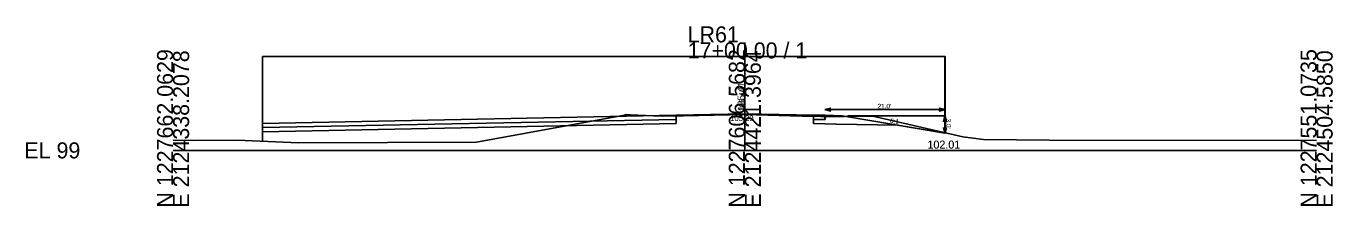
# Model space of a CAD drawing. Extents: x 2126751 to 2128979, y 1225108 to 1234639.
# Drawn here: x 2127750.9 to 2127979.4, y 1232107.5 to 1232138.9 of the extents above; entities that cross this region are included whole.
import ezdxf

# ---------------------------------------------------------------- set-up
doc = ezdxf.new("R2010")
doc.units = 0
for name, color, linetype in [('XS_CELL', 7, 'Continuous'), ('XS_M_DITCH', 7, 'Continuous'), ('XS_P_FINISHED_GRADE', 7, 'Continuous'), ('XS_P_FINISHED_GRADE_ELEV_TX', 7, 'Continuous'), ('XS_P_SUBGRADE_GRANULAR', 7, 'Continuous'), ('XS_P_SUBGRADE_LEVELING', 7, 'Continuous'), ('XS_P_SUBGRADE_PAVEMENT', 7, 'Continuous'), ('XS_P_TX_CLEARZONE', 7, 'Continuous'), ('XS_P_TX_DCH', 7, 'Continuous'), ('XS_P_TX_FS_BS', 7, 'Continuous'), ('XS_X_GROUND', 7, 'Continuous'), ('XS_X_GROUND_TX', 7, 'Continuous')]:
    doc.layers.add(name, color=color, linetype=linetype)

msp = doc.modelspace()

# ---------------------------------------------------------------- linework, layer by layer
at = {"layer": 'XS_CELL'}
for p, q in [((2127876.61, 1232117.21), (2127876.61, 1232136.08)), ((2127776.61, 1232117.21), (2127876.61, 1232117.21)), ((2127876.61, 1232117.21), (2127976.61, 1232117.21))]:
    msp.add_line(p, q, dxfattribs=at)
at = {"layer": 'XS_M_DITCH'}
for p, q in [((2127792.23, 1232118.82), (2127792.23, 1232133.62)), ((2127792.23, 1232133.62), (2127911.61, 1232133.62)), ((2127792.23, 1232118.82), (2127792.23, 1232133.62)), ((2127792.23, 1232133.62), (2127911.63, 1232133.62)), ((2127911.61, 1232133.62), (2127911.61, 1232120.22)), ((2127911.63, 1232133.62), (2127911.63, 1232120.22))]:
    msp.add_line(p, q, dxfattribs=at)
at = {"layer": 'XS_P_FINISHED_GRADE'}
for p, q in [((2127864.61, 1232123.38), (2127792.23, 1232121.93)), ((2127864.61, 1232123.38), (2127792.23, 1232121.93)), ((2127864.61, 1232123.38), (2127876.61, 1232123.62)), ((2127864.61, 1232123.38), (2127876.61, 1232123.62)), ((2127876.61, 1232123.62), (2127888.61, 1232123.38)), ((2127876.61, 1232123.62), (2127888.61, 1232123.38)), ((2127888.61, 1232123.38), (2127890.61, 1232123.34)), ((2127888.61, 1232123.38), (2127890.63, 1232123.34)), ((2127890.61, 1232123.34), (2127893.61, 1232123.22)), ((2127890.63, 1232123.34), (2127893.63, 1232123.22)), ((2127893.61, 1232123.22), (2127911.61, 1232120.22)), ((2127893.63, 1232123.22), (2127911.63, 1232120.22)), ((2127792.23, 1232121.93), (2127792.23, 1232118.82)), ((2127792.23, 1232121.93), (2127792.23, 1232118.82)), ((2127911.61, 1232120.22), (2127911.7, 1232120.25)), ((2127911.63, 1232120.22), (2127911.71, 1232120.25))]:
    msp.add_line(p, q, dxfattribs=at)
at = {"layer": 'XS_P_SUBGRADE_GRANULAR'}
for p, q in [((2127864.61, 1232121.88), (2127864.61, 1232122.63)), ((2127864.61, 1232121.88), (2127864.61, 1232122.63)), ((2127888.61, 1232121.88), (2127888.61, 1232122.63)), ((2127888.61, 1232121.88), (2127888.61, 1232122.63)), ((2127864.61, 1232121.88), (2127792.23, 1232120.43)), ((2127864.61, 1232121.88), (2127792.23, 1232120.43)), ((2127888.61, 1232121.88), (2127890.61, 1232121.84)), ((2127888.61, 1232121.88), (2127890.63, 1232121.84)), ((2127890.61, 1232121.84), (2127892.61, 1232121.8)), ((2127890.63, 1232121.84), (2127892.63, 1232121.8)), ((2127892.61, 1232121.8), (2127903.43, 1232121.59)), ((2127892.63, 1232121.8), (2127903.45, 1232121.59))]:
    msp.add_line(p, q, dxfattribs=at)
at = {"layer": 'XS_P_SUBGRADE_LEVELING'}
for p, q in [((2127864.61, 1232123.38), (2127864.61, 1232123.23)), ((2127864.61, 1232123.38), (2127864.61, 1232123.23)), ((2127864.61, 1232123.23), (2127865.9, 1232123.26)), ((2127864.61, 1232123.23), (2127865.9, 1232123.26)), ((2127865.9, 1232123.26), (2127876.58, 1232123.5)), ((2127865.9, 1232123.26), (2127876.58, 1232123.5)), ((2127876.58, 1232123.5), (2127888.61, 1232123.14)), ((2127876.58, 1232123.5), (2127888.61, 1232123.14)), ((2127888.61, 1232123.38), (2127888.61, 1232123.14)), ((2127888.61, 1232123.38), (2127888.61, 1232123.14))]:
    msp.add_line(p, q, dxfattribs=at)
at = {"layer": 'XS_P_SUBGRADE_PAVEMENT'}
for p, q in [((2127864.61, 1232122.63), (2127792.23, 1232121.18)), ((2127864.61, 1232122.63), (2127792.23, 1232121.18)), ((2127864.61, 1232122.63), (2127864.61, 1232123.23)), ((2127888.61, 1232122.63), (2127888.61, 1232123.14)), ((2127888.61, 1232122.63), (2127888.61, 1232123.14)), ((2127888.61, 1232122.63), (2127890.61, 1232122.59)), ((2127888.61, 1232122.63), (2127890.63, 1232122.59)), ((2127890.61, 1232122.59), (2127890.61, 1232123.34)), ((2127890.63, 1232122.59), (2127890.63, 1232123.34))]:
    msp.add_line(p, q, dxfattribs=at)
at = {"layer": 'XS_P_TX_CLEARZONE'}
for p, q in [((2127890.61, 1232124.34), (2127891.61, 1232124.59)), ((2127890.63, 1232124.34), (2127891.63, 1232124.59)), ((2127911.61, 1232124.34), (2127910.61, 1232124.59)), ((2127911.63, 1232124.34), (2127910.63, 1232124.59)), ((2127890.61, 1232124.34), (2127891.61, 1232124.09)), ((2127890.61, 1232124.34), (2127911.61, 1232124.34)), ((2127890.63, 1232124.34), (2127891.63, 1232124.09)), ((2127890.63, 1232124.34), (2127911.63, 1232124.34)), ((2127894.61, 1232123.22), (2127911.61, 1232123.22)), ((2127894.63, 1232123.22), (2127911.63, 1232123.22)), ((2127911.61, 1232124.34), (2127910.61, 1232124.09)), ((2127911.63, 1232124.34), (2127910.63, 1232124.09)), ((2127911.61, 1232123.22), (2127911.36, 1232122.22)), ((2127911.63, 1232123.22), (2127911.38, 1232122.22)), ((2127911.61, 1232123.22), (2127911.61, 1232120.22)), ((2127911.61, 1232123.22), (2127911.86, 1232122.22)), ((2127911.63, 1232123.22), (2127911.63, 1232120.22)), ((2127911.63, 1232123.22), (2127911.88, 1232122.22)), ((2127911.61, 1232120.22), (2127911.36, 1232121.22)), ((2127911.63, 1232120.22), (2127911.38, 1232121.22)), ((2127911.61, 1232120.22), (2127911.86, 1232121.22)), ((2127911.63, 1232120.22), (2127911.88, 1232121.22))]:
    msp.add_line(p, q, dxfattribs=at)
at = {"layer": 'XS_X_GROUND'}
for p, q in [((2127829.66, 1232118.65), (2127855.57, 1232123.38)), ((2127855.57, 1232123.38), (2127855.94, 1232123.47)), ((2127855.94, 1232123.47), (2127856.56, 1232123.44)), ((2127856.56, 1232123.44), (2127861.96, 1232123.17)), ((2127861.96, 1232123.17), (2127865.9, 1232123.26)), ((2127865.9, 1232123.26), (2127876.58, 1232123.5)), ((2127876.58, 1232123.5), (2127889.88, 1232123.11)), ((2127889.88, 1232123.11), (2127890.83, 1232123.07)), ((2127890.83, 1232123.07), (2127894.02, 1232123.12)), ((2127894.02, 1232123.12), (2127898.97, 1232123.19)), ((2127898.97, 1232123.19), (2127914.72, 1232119.55)), ((2127776.61, 1232118.97), (2127780.26, 1232118.95)), ((2127780.26, 1232118.95), (2127787.83, 1232119)), ((2127787.83, 1232119), (2127798.57, 1232118.54)), ((2127798.57, 1232118.54), (2127829.66, 1232118.65)), ((2127914.72, 1232119.55), (2127918.37, 1232119.1)), ((2127918.37, 1232119.1), (2127929.92, 1232119.02)), ((2127929.92, 1232119.02), (2127976.61, 1232118.92))]:
    msp.add_line(p, q, dxfattribs=at)

# ---------------------------------------------------------------- texts
at = {"layer": 'XS_CELL'}
for s, p in [('LR61', (2127866.61, 1232136.08)), ('17+00.00 / 1', (2127866.61, 1232133.28)), ('EL 99', (2127750.61, 1232115.81))]:
    msp.add_text(s, height=2.8, dxfattribs=at).set_placement(p)
for s, p in [('N 1227662.0629', (2127776.61, 1232107.21)), ('E 2124338.2078', (2127779.41, 1232107.21)), ('N 1227606.5682', (2127876.61, 1232107.21)), ('E 2124421.3964', (2127879.41, 1232107.21)), ('N 1227551.0735', (2127976.61, 1232107.21)), ('E 2124504.5850', (2127979.41, 1232107.21))]:
    msp.add_text(s, height=2.8, rotation=90, dxfattribs=at).set_placement(p)
at = {"layer": 'XS_P_FINISHED_GRADE_ELEV_TX'}
for height in [1.25, 1]:
    msp.add_text(' 105.41', height=height, rotation=90, dxfattribs=at).set_placement((2127876.61, 1232123.62))
at = {"layer": 'XS_P_TX_CLEARZONE'}
for p in [(2127899.82, 1232124.54), (2127899.85, 1232124.54)]:
    msp.add_text("21.0'", height=0.8, dxfattribs=at).set_placement(p)
for p in [(2127911.81, 1232122.75), (2127911.83, 1232122.75)]:
    msp.add_text("3.0'", height=0.8, rotation=270, dxfattribs=at).set_placement(p)
at = {"layer": 'XS_P_TX_DCH'}
for p in [(2127908.54, 1232117.52), (2127908.57, 1232117.52)]:
    msp.add_text('102.01', height=1.4, dxfattribs=at).set_placement(p)
at = {"layer": 'XS_P_TX_FS_BS'}
for p in [(2127901.95, 1232122.03), (2127901.98, 1232122.03)]:
    msp.add_text('6:1', height=0.8, rotation=350.5377, dxfattribs=at).set_placement(p)
at = {"layer": 'XS_X_GROUND_TX'}
msp.add_text('105.29', height=1, dxfattribs=at).set_placement((2127874.05, 1232122.33))

doc.saveas('drawing.dxf')
